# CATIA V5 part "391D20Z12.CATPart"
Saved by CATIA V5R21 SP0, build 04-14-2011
Part number: 391D20Z12
Bounding box of the stored display mesh (mm): x -48.732 to 48.732, y -14 to 14, z -48.732 to 48.732
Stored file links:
  C:\Users\ALI OZGUN\Desktop\alhan\391D20Z12.CATPart
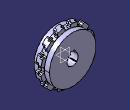
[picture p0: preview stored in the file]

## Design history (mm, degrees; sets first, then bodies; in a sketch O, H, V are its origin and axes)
Body1 (main body)
  Sketch1 on zx-plane, origin (0, 0, 0), H (-1, 0, 0), V (0, 0, 1)
    circle A1 centre (0, 0) radius 42.25
    radius A1 = 42.25
  Pad1: profile Sketch1, direction (0, 1, 0), length 14
  Sketch2 on zx-plane, origin (0, 0, 0), H (-1, 0, 0), V (0, 0, 1)
    circle A1 centre (0, 0) radius 49
    radius A1 = 49
  Pad2: profile Sketch2, direction (0, 1, 0), length 5
  Sketch3 on end face of Pad2, origin (0, 5, 0), H (-1, 0, 0), V (0, 0, 1)
    point P1 (-6.5, 48.567)
    line L1 (-6.5, 48.567) -> (-4.25, 42.7895)
    point P2 (-4.25, 42.7895)
    arc A1 centre (0, 0) radius 43 from (4.25, 42.7895) to (-4.25, 42.7895) ccw
    reference projected circle E1 centre (0, 0) radius 49 from edge [face of Pad2 from Sketch2.A1 | end face of Pad2]
    point P3 (4.25, 42.7895)
    point P4 (6.5, 48.567)
    line L2 (6.5, 48.567) -> (4.25, 42.7895)
    radius A1 = 43
    distance P1 V = 6.5
    distance P2 V = 4.25
    coincidence: P1 E1
    symmetry: P2 P3 V, P1 P4 V, L1 L2 V
  Pocket1: profile Sketch3, direction (0, -1, 0), length 5
  CircPattern1: of Pocket1, instances 12, angular step 30, axis from face of Pad1 from Sketch1.A1
  Fillet1: radius 2, on edge [face of CircPattern1 | face of Pad2 from Sketch2.A1] (x11); edge [face of Pad2 from Sketch2.A1 | face of CircPattern1] (x11); edge [face of Pocket1 from Sketch3.L1 | face of Pad2 from Sketch2.A1]; edge [face of Pad2 from Sketch2.A1 | face of Pocket1 from Sketch3.L2]; edge [face of CircPattern1 | face of CircPattern1] (x22); edge [face of Pocket1 from Sketch3.L2 | face of Pocket1 from Sketch3.A1]; edge [face of Pocket1 from Sketch3.A1 | face of Pocket1 from Sketch3.L1]
Body2
  Solid1: linked copy from another document
  Body3
    Solid2: linked copy from another document
    Symmetry1: ToTransfor Solid2, Reference face of Solid2
    Rotate1: ToTransfor Symmetry1, Angle 3.5, Axis Sketch4
    Sketch4 on yz-plane, origin (0, 0, 0), H (0, 1, 0), V (0, 0, 1)
      line L1 (68.9983, 0) -> (-60.7772, 0)
      point P1 (68.9983, 0)
      coincidence: P1 H
      horizontal: L1 H
  Add1: tool Body3
  Sketch5 on face of Solid1, origin (0, 14, 0), H (-1, 0, 0), V (0, 0, 1)
    arc A1 centre (0, 0) radius 10 from (-4, 9.1652) to (4, 9.1652) ccw
    line L1 (4, 13.1652) -> (-4, 13.1652)
    line L2 (-4, 13.1652) -> (-4, 9.1652)
    line L3 (4, 9.1652) -> (4, 13.1652)
    length L2 = 4
    length L1 = 8
    radius A1 = 10
    distance L3 V = 4
    horizontal: L1 H
    vertical: L2 V, L3 V
  Pocket2: profile Sketch5, direction (0, -1, 0), through (limit type 6)
  Sketch6 on face of Solid1, origin (0, 14, 0), H (-1, 0, 0), V (0, 0, 1)
    construction line L1 (-18.4923, 18.4923) -> (16.4725, -16.4725)
    axis line L2 (23.8397, 23.8397) -> (-21.8636, -21.8636)
    construction circle A1 centre (0, 0) radius 11
    arc A2 centre (-10.0747, -10.0747) radius 18 from (-7.7782, 7.7782) to (0, 4.8417) cw
    point P6 (-7.7782, 7.7782)
    point P7 (7.7782, -7.7782)
    point P8 (2.6532, 2.6532)
    point P9 (7.7782, -7.7782)
    point P10 (-7.7782, 7.7782)
    arc A3 centre (10.0747, 10.0747) radius 18 from (-7.7782, 7.7782) to (-4.8417, 0) ccw
    point P12 (-7.7782, -7.7782)
    point P13 (7.7782, 7.7782)
    arc A4 centre (-10.0747, 10.0747) radius 18 from (7.7782, 7.7782) to (4.8417, 0) cw
    point P15 (-7.7782, -7.7782)
    point P16 (7.7782, 7.7782)
    arc A5 centre (10.0747, -10.0747) radius 18 from (7.7782, 7.7782) to (0, 4.8417) ccw
    arc A6 centre (10.0747, -10.0747) radius 18 from (-4.8417, 0) to (-7.7782, -7.7782) ccw
    arc A7 centre (10.0747, 10.0747) radius 18 from (0, -4.8417) to (7.7782, -7.7782) ccw
    arc A8 centre (-10.0747, 10.0747) radius 18 from (0, -4.8417) to (-7.7782, -7.7782) cw
    point P20 (4.8417, 0)
    arc A9 centre (-10.0747, -10.0747) radius 18 from (4.8417, 0) to (7.7782, -7.7782) cw
    angle L1 V = 45
    angle V L2 = 45
    radius A1 = 11
    radius A2 = 18
    coincidence: L1 O, L2 O, P6 A1, P6 L1, P7 A1, P7 L1, A2 P8, P8 L2, A5 A6, A3 A7, A4 A8, A2 P20, A2 A9, P6 P10, P7 P9, P12 P15, P13 P16
    symmetry: P7 P9 L1, P6 P10 L1, A2 A3 L1, P9 P12 V, P10 P13 V, A3 A4 V, P7 P15 V, P6 P16 V, A2 A5 V
  Pocket3: profile Sketch6, direction (0, -1, 0), through (limit type 6)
